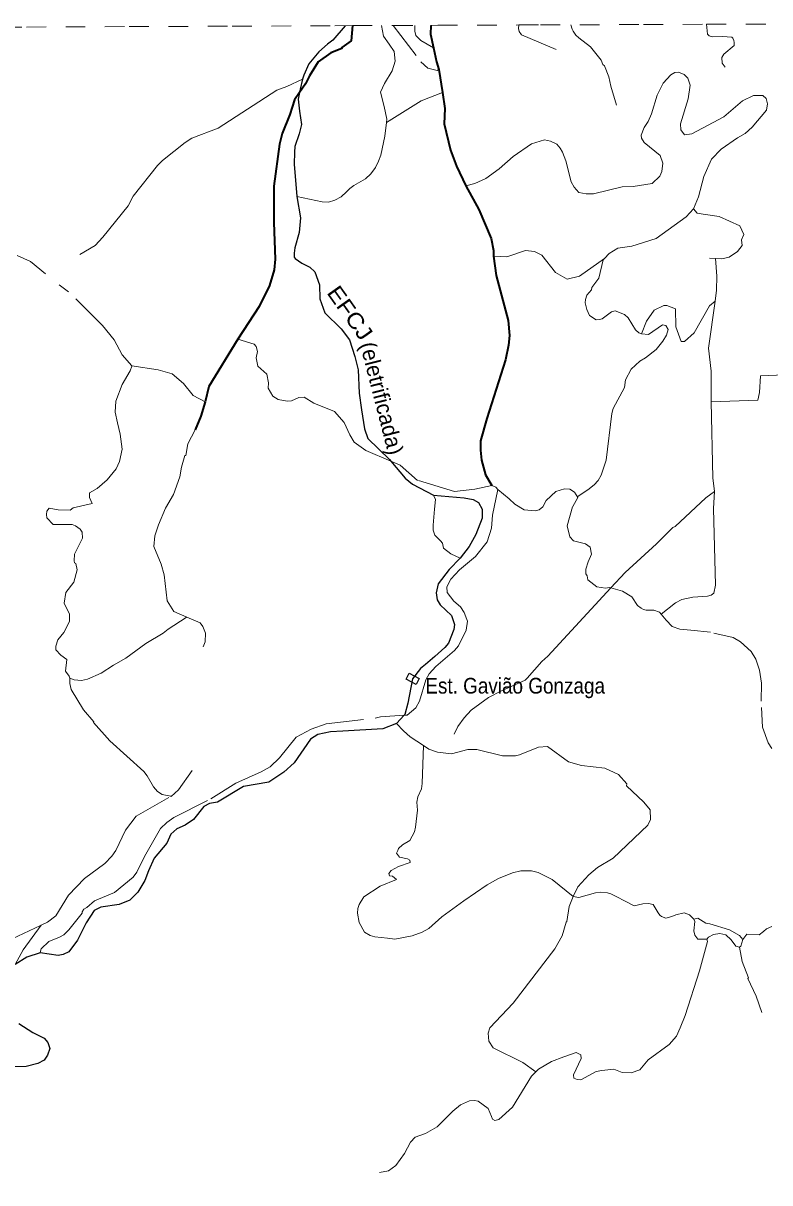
# Model space of a CAD drawing. Extents: x 423 to 448.8, y 7456.3 to 7484.
# Drawn here: x 436.07 to 439.88, y 7478.1 to 7484.01 of the extents above; entities that cross this region are included whole.
import ezdxf
from ezdxf.enums import TextEntityAlignment as Align

# ---------------------------------------------------------------- set-up
doc = ezdxf.new("R2010")
doc.units = 0
doc.header["$LTSCALE"] = 0.032
for name, pattern in [('LONG_DASHED', [7.5, 6, -1.5]), ('MEDIUM_DASHED', [4.5, 3, -1.5]), ('SHORT_DASHED', [2.7, 1.5, -1.2])]:
    doc.linetypes.add(name, pattern=pattern)
for name, color, linetype, lineweight in [('15', 7, 'Continuous', 25), ('2', 7, 'Continuous', 35), ('28', 7, 'Continuous', 25), ('35', 7, 'SHORT_DASHED', 13), ('5', 7, 'LONG_DASHED', 13), ('6', 7, 'MEDIUM_DASHED', 13), ('7', 7, 'Continuous', 13)]:
    doc.layers.add(name, color=color, linetype=linetype, lineweight=lineweight)
doc.layers.add('61', color=7, linetype='Continuous')

msp = doc.modelspace()

# ---------------------------------------------------------------- linework, layer by layer
at = {"layer": '15'}
for points in [[(437.7138, 7483.9944), (437.6506, 7483.9214), (437.6237, 7483.8998), (437.5792, 7483.862), (437.5283, 7483.8001), (437.5023, 7483.7419), (437.4969, 7483.7213), (437.4837, 7483.6711), (437.4807, 7483.6534), (437.475, 7483.6196), (437.4803, 7483.5594), (437.4915, 7483.4905), (437.4798, 7483.444), (437.4567, 7483.3794), (437.4548, 7483.35), (437.4536, 7483.2887), (437.4671, 7483.1237), (437.4865, 7483.0149), (437.4794, 7482.9405), (437.4572, 7482.8629), (437.4545, 7482.8364), (437.4535, 7482.8225), (437.4545, 7482.8148), (437.4585, 7482.8082), (437.4934, 7482.7843), (437.5337, 7482.7649), (437.5586, 7482.741), (437.5825, 7482.6742), (437.585, 7482.6029), (437.6103, 7482.5325), (437.6934, 7482.451), (437.7357, 7482.3946), (437.7627, 7482.3094), (437.7795, 7482.241), (437.7856, 7482.1232), (437.7961, 7482.038), (437.8125, 7481.9408), (437.8289, 7481.8915), (437.939, 7481.7853), (437.947, 7481.7757), (438.0191, 7481.6901), (438.0559, 7481.6582), (438.1629, 7481.6029), (438.3194, 7481.59), (438.3653, 7481.5813), (438.3936, 7481.5648), (438.4113, 7481.5316), (438.4122, 7481.4853), (438.3798, 7481.4029), (438.3449, 7481.3422), (438.2989, 7481.2825), (438.2443, 7481.2246), (438.1877, 7481.1508), (438.1767, 7481.106), (438.1822, 7481.0689), (438.1983, 7481.0447), (438.255, 7480.9897), (438.2714, 7480.9443), (438.2674, 7480.9193), (438.2396, 7480.8488), (438.2207, 7480.8265), (438.1707, 7480.7817), (438.1236, 7480.7407), (438.097, 7480.72), (438.0559, 7480.667), (438.0335, 7480.544), (438.017, 7480.4859), (438.0135, 7480.482), (437.9759, 7480.4401), (437.9058, 7480.4132), (437.7025, 7480.4), (437.6393, 7480.3971), (437.5752, 7480.3841), (437.5372, 7480.3602), (437.4547, 7480.2401), (437.4019, 7480.1912), (437.3248, 7480.1409), (437.1964, 7480.118), (437.0625, 7480.0388), (437.0222, 7480.0324), (436.9933, 7480.0174), (436.9416, 7479.9506), (436.8993, 7479.9212), (436.8555, 7479.9033), (436.8256, 7479.8754), (436.8047, 7479.8305), (436.7413, 7479.7535), (436.7124, 7479.6886), (436.6932, 7479.6391), (436.6579, 7479.5808), (436.6171, 7479.5389), (436.5619, 7479.5185), (436.4695, 7479.5039), (436.4352, 7479.4876), (436.3939, 7479.4249), (436.3501, 7479.3365), (436.3053, 7479.277), (436.2775, 7479.263), (436.2514, 7479.2583), (436.1598, 7479.2719), (436.092, 7479.2491)], [(436.092, 7479.2491), (436.0323, 7479.2122)], [(436.0507, 7478.9116), (436.1219, 7478.8653), (436.18, 7478.8372), (436.1993, 7478.8145), (436.2093, 7478.7841), (436.1974, 7478.7502), (436.1806, 7478.7255), (436.1474, 7478.7078), (436.0894, 7478.6929), (436.0138, 7478.6899)]]:
    msp.add_lwpolyline(points, dxfattribs=at)
at = {"layer": '2'}
for points in [[(437.7508, 7483.9946), (437.7449, 7483.9172), (437.6963, 7483.8835), (437.6968, 7483.8788), (437.641, 7483.8557), (437.5765, 7483.8101), (437.5312, 7483.7394), (437.5108, 7483.6986), (437.4807, 7483.6534), (437.4562, 7483.6166), (437.4321, 7483.5429), (437.3919, 7483.4452), (437.379, 7483.3902), (437.3507, 7483.1772), (437.3498, 7482.9917), (437.3567, 7482.8045), (437.3524, 7482.7512), (437.3275, 7482.6705), (437.2759, 7482.564), (437.1662, 7482.3978), (437.0199, 7482.1557), (437.0013, 7482.0778), (436.9791, 7482.0056), (436.9495, 7481.9352)], [(438.1502, 7483.9962), (438.1491, 7483.9506), (438.1636, 7483.8811), (438.1784, 7483.8101), (438.1915, 7483.7708), (438.2089, 7483.6534), (438.2208, 7483.5731), (438.2176, 7483.4947), (438.2499, 7483.361), (438.28, 7483.2786), (438.3288, 7483.1789), (438.3942, 7483.0587), (438.457, 7482.9098), (438.469, 7482.8493), (438.47, 7482.8201), (438.4827, 7482.722), (438.5436, 7482.4919), (438.5505, 7482.4163), (438.5462, 7482.3665), (438.5308, 7482.2926), (438.4346, 7481.9928), (438.4036, 7481.8804), (438.4028, 7481.8323), (438.4088, 7481.7807), (438.4294, 7481.7069), (438.4602, 7481.6527)]]:
    msp.add_lwpolyline(points, dxfattribs=at)
at = {"layer": '28'}
msp.add_lwpolyline([(438.0402, 7480.6953), (438.0907, 7480.6688), (438.075, 7480.6388), (438.0245, 7480.6653)], close=True, dxfattribs=at)
at = {"layer": '35'}
for points in [[(435.5128, 7483.9852), (435.5662, 7483.9854), (436.09, 7483.9876), (436.6139, 7483.9898), (437.1378, 7483.992), (437.6616, 7483.9942), (437.7508, 7483.9946), (437.9587, 7483.9954), (438.1502, 7483.9962)], [(438.1502, 7483.9962), (438.1855, 7483.9963), (438.5987, 7483.998)], [(438.5987, 7483.998), (438.7093, 7483.9984), (439.2332, 7484.0005), (439.5546, 7484.0018)], [(439.5546, 7484.0018), (439.7571, 7484.0026), (440.2809, 7484.0047), (440.8048, 7484.0067), (440.9332, 7484.0072)]]:
    msp.add_lwpolyline(points, dxfattribs=at)
at = {"layer": '5'}
for points in [[(437.8985, 7483.9951), (437.9098, 7483.9407), (437.9376, 7483.9009), (437.9634, 7483.863), (437.9692, 7483.8136), (437.9536, 7483.7646), (437.9146, 7483.7004), (437.8937, 7483.6555), (437.9125, 7483.5827), (437.9255, 7483.5179), (437.9238, 7483.5016), (437.9165, 7483.4311), (437.8946, 7483.3354), (437.8835, 7483.3039)], [(437.9587, 7483.9954), (438.0988, 7483.811), (438.1351, 7483.7786), (438.1819, 7483.7657), (438.1915, 7483.7708)], [(438.0686, 7483.9958), (438.0683, 7483.9662), (438.0744, 7483.9439), (438.0997, 7483.9191), (438.1636, 7483.8811)], [(438.5987, 7483.998), (438.5969, 7483.9794), (438.6005, 7483.9647), (438.6118, 7483.9475), (438.8434, 7483.8505)], [(439.0967, 7483.5888), (439.0673, 7483.6858), (439.0572, 7483.7346), (439.0349, 7483.7904), (439.0271, 7483.7964), (439.0177, 7483.8188), (438.9627, 7483.8866), (438.9043, 7483.9321), (438.8885, 7483.9466), (438.875, 7483.9665), (438.87, 7483.977), (438.8639, 7483.999)], [(439.5546, 7484.0018), (439.5588, 7483.952), (439.5677, 7483.9434), (439.583, 7483.9375), (439.6355, 7483.9398), (439.6826, 7483.9363), (439.6888, 7483.9303), (439.6931, 7483.9188), (439.6957, 7483.9084), (439.6948, 7483.8935), (439.6431, 7483.85), (439.6321, 7483.8324), (439.6338, 7483.8044), (439.6495, 7483.7835)], [(437.0013, 7482.0778), (436.9387, 7482.1108), (436.8906, 7482.172), (436.8323, 7482.2216), (436.7609, 7482.242), (436.6269, 7482.2621), (436.5774, 7482.3175), (436.5366, 7482.3934), (436.4769, 7482.4672), (436.305, 7482.6387), (436.2569, 7482.6737)], [(436.1598, 7479.2719), (436.1604, 7479.2739), (436.1654, 7479.2914), (436.2033, 7479.3287), (436.2583, 7479.351), (436.2797, 7479.3639), (436.3055, 7479.3879), (436.3742, 7479.4738), (436.3733, 7479.4807), (436.3819, 7479.4936), (436.3982, 7479.5022), (436.436, 7479.5365), (436.5385, 7479.5786), (436.6344, 7479.6568), (436.6524, 7479.6817), (436.6923, 7479.7627), (436.7736, 7479.905), (436.8053, 7479.9359), (436.8416, 7479.9605), (437.0286, 7480.0562), (437.1566, 7480.1352), (437.2854, 7480.1927), (437.331, 7480.2185), (437.379, 7480.264), (437.4648, 7480.3698), (437.5397, 7480.4108), (437.617, 7480.4383), (437.866, 7480.4675), (437.8941, 7480.4744), (438.0135, 7480.482), (438.0292, 7480.483), (438.0738, 7480.5199), (438.0918, 7480.5543), (438.1253, 7480.6625), (438.1408, 7480.6926), (438.176, 7480.7303), (438.2705, 7480.8111), (438.2903, 7480.836), (438.3298, 7480.915), (438.3367, 7480.9605), (438.334, 7480.97), (438.3203, 7481.0052), (438.3013, 7481.0338), (438.268, 7481.063), (438.2338, 7481.1066), (438.2319, 7481.1358), (438.2522, 7481.1748), (438.2959, 7481.2227), (438.3775, 7481.2905), (438.4373, 7481.3657), (438.4586, 7481.4355), (438.4638, 7481.5006), (438.4908, 7481.6314), (438.4815, 7481.6444), (438.4602, 7481.6527), (438.3742, 7481.6333), (438.2705, 7481.6212), (438.0819, 7481.6783), (437.9931, 7481.7561), (437.947, 7481.7757), (437.8191, 7481.8303), (437.7599, 7481.8731), (437.7379, 7481.9106), (437.7081, 7481.9732), (437.66, 7482.0289), (437.5534, 7482.071), (437.5044, 7482.1028), (437.4778, 7482.1011), (437.44, 7482.083), (437.4177, 7482.0822), (437.373, 7482.0899), (437.3447, 7482.1071), (437.3206, 7482.1483), (437.3224, 7482.1744), (437.315, 7482.2186), (437.2687, 7482.2594), (437.2604, 7482.3025), (437.2678, 7482.334), (437.2597, 7482.3596), (437.2493, 7482.3716), (437.1662, 7482.3978)], [(436.9495, 7481.9352), (436.9125, 7481.8647), (436.9014, 7481.8054), (436.8977, 7481.8054), (436.8792, 7481.746), (436.871, 7481.6957), (436.8385, 7481.607), (436.7978, 7481.5365), (436.7624, 7481.4509), (436.7435, 7481.396), (436.7383, 7481.341), (436.7761, 7481.2517), (436.7916, 7481.1967), (436.8067, 7481.0643), (436.8414, 7481.0103), (436.9072, 7480.9821), (436.9754, 7480.9528), (436.9891, 7480.9339), (437.003, 7480.8993), (437.0011, 7480.8564), (436.99, 7480.8298)], [(436.1644, 7479.4118), (436.1968, 7479.4271), (436.2403, 7479.4595), (436.3046, 7479.5658), (436.3862, 7479.6508), (436.4901, 7479.7272), (436.5245, 7479.7641), (436.5451, 7479.7934), (436.5949, 7479.8964), (436.6486, 7479.9684), (436.8268, 7480.0682), (436.8646, 7480.1025), (436.9341, 7480.2004)], [(436.1644, 7479.4118), (436.1624, 7479.4108), (435.9701, 7479.3194), (435.9024, 7479.3003), (435.7206, 7479.321), (435.6021, 7479.345), (435.5591, 7479.3442), (435.5231, 7479.3253), (435.508, 7479.2673), (435.5064, 7479.2611), (435.5092, 7479.2351), (435.5286, 7479.1744), (435.6742, 7479.0513), (435.7103, 7478.9861), (435.7511, 7478.8627), (435.766, 7478.7426), (435.782, 7478.4926), (435.7801, 7478.418), (435.7662, 7478.3415), (435.744, 7478.266), (435.7079, 7478.196), (435.6699, 7478.1428), (435.6394, 7478.077)], [(436.0323, 7479.2122), (436.0728, 7479.2872), (436.1644, 7479.4118)]]:
    msp.add_lwpolyline(points, dxfattribs=at)
at = {"layer": '6'}
for points in [[(436.0422, 7482.8245), (436.1102, 7482.7932), (436.2569, 7482.6737)], [(438.6838, 7481.5228), (438.6255, 7481.529), (438.5776, 7481.5569), (438.5488, 7481.5834), (438.4908, 7481.6314)], [(439.8868, 7480.3129), (439.8688, 7480.3413), (439.8396, 7480.4211), (439.8328, 7480.5534), (439.8344, 7480.6453), (439.825, 7480.7106), (439.8052, 7480.7673), (439.7821, 7480.8059), (439.7271, 7480.8557), (439.6899, 7480.8783), (439.5749, 7480.9047), (439.4744, 7480.9147), (439.4185, 7480.9209), (439.3793, 7480.9341), (439.3484, 7480.9661), (439.3239, 7480.9963), (439.3154, 7481.0068), (439.2861, 7481.0165), (439.2467, 7481.0173), (439.2334, 7481.0199), (439.2207, 7481.0267), (439.2026, 7481.0413), (439.1738, 7481.0852), (439.126, 7481.1141), (439.0665, 7481.1304), (439.0598, 7481.1323), (439.0392, 7481.1289), (438.9962, 7481.1357), (438.9507, 7481.1718), (438.9473, 7481.1915), (438.9404, 7481.2027), (438.9395, 7481.2259), (438.9509, 7481.2633), (438.9685, 7481.3026), (438.9619, 7481.3375), (438.9378, 7481.3556), (438.8768, 7481.371), (438.8585, 7481.391), (438.8448, 7481.4471), (438.8726, 7481.5457), (438.8983, 7481.5918), (438.8824, 7481.6182), (438.8577, 7481.6326), (438.8304, 7481.6354), (438.7875, 7481.6222), (438.7381, 7481.5754), (438.72, 7481.544), (438.7023, 7481.5283), (438.6838, 7481.5228)]]:
    msp.add_lwpolyline(points, dxfattribs=at)
at = {"layer": '7'}
msp.add_line((439.5691, 7482.8103), (439.6007, 7482.8088), dxfattribs=at)
for points in [[(438.3288, 7483.1789), (438.3741, 7483.1912), (438.4296, 7483.2163), (438.4989, 7483.2647), (438.5694, 7483.328), (438.663, 7483.3927), (438.7283, 7483.4133), (438.7592, 7483.4065), (438.7927, 7483.3902), (438.809, 7483.3704), (438.821, 7483.3507), (438.8373, 7483.306), (438.8657, 7483.1986), (438.8803, 7483.172), (438.9043, 7483.1454), (438.9413, 7483.1377), (438.9782, 7483.1377), (439.1242, 7483.1729), (439.18, 7483.1746), (439.2771, 7483.191), (439.3174, 7483.2287), (439.3261, 7483.2519), (439.3312, 7483.2948), (439.3175, 7483.3326), (439.2376, 7483.3996), (439.2238, 7483.4211), (439.2213, 7483.4374), (439.2367, 7483.4752), (439.2564, 7483.5061), (439.2736, 7483.5456), (439.3037, 7483.641), (439.3329, 7483.7019), (439.3724, 7483.744), (439.393, 7483.7561), (439.411, 7483.7578), (439.4411, 7483.7458), (439.4591, 7483.7269), (439.4712, 7483.6916), (439.4609, 7483.6221), (439.4222, 7483.495), (439.4231, 7483.4641), (439.4429, 7483.4391), (439.4797, 7483.4435), (439.6428, 7483.5302), (439.7374, 7483.6109), (439.7941, 7483.6393), (439.8405, 7483.6384), (439.8576, 7483.6238), (439.8654, 7483.5963), (439.8603, 7483.5645), (439.7864, 7483.4769), (439.7512, 7483.4452), (439.7116, 7483.4237), (439.6283, 7483.3661), (439.5803, 7483.3146), (439.5408, 7483.2261), (439.5132, 7483.1231), (439.4875, 7483.0621)], [(437.4969, 7483.7213), (437.4165, 7483.6842), (437.3655, 7483.6668), (437.0675, 7483.4728), (436.9333, 7483.422), (436.8981, 7483.3996), (436.783, 7483.3069), (436.7581, 7483.282), (436.6343, 7483.1254), (436.6084, 7483.0766), (436.479, 7482.9164), (436.4403, 7482.8741), (436.3621, 7482.8283)], [(437.9238, 7483.5016), (438.1005, 7483.612), (438.2089, 7483.6534)], [(437.8835, 7483.3039), (437.8682, 7483.2723), (437.8451, 7483.2395), (437.8175, 7483.2135), (437.7579, 7483.1803), (437.7381, 7483.1643), (437.7207, 7483.1474), (437.6934, 7483.1234), (437.6606, 7483.1051), (437.6285, 7483.0963), (437.5972, 7483.0972), (437.4671, 7483.1237)], [(439.4875, 7483.0621), (439.4506, 7483.0208), (439.2977, 7482.911), (439.1732, 7482.8714), (439.1028, 7482.8611), (439.0581, 7482.8345), (439.0349, 7482.8087)], [(439.6007, 7482.8088), (439.6318, 7482.8073), (439.6691, 7482.8157), (439.7129, 7482.8446), (439.7368, 7482.8745), (439.7333, 7482.9039), (439.7443, 7482.9308), (439.7244, 7482.9747), (439.6194, 7483.0221), (439.5368, 7483.034), (439.5068, 7483.04), (439.4875, 7483.0621)], [(439.0349, 7482.8087), (438.9069, 7482.718), (438.8451, 7482.7036), (438.7859, 7482.7368), (438.715, 7482.8247), (438.6783, 7482.8435), (438.6316, 7482.8489), (438.5375, 7482.8175), (438.47, 7482.8201)], [(439.0349, 7482.8087), (439.0288, 7482.8019), (439.0066, 7482.7091), (438.9705, 7482.6602), (438.9679, 7482.649), (438.9447, 7482.6215), (438.9378, 7482.6001), (438.9361, 7482.582), (438.9447, 7482.5485), (438.9585, 7482.5184), (438.9919, 7482.4961), (439.01, 7482.497), (439.0228, 7482.5013), (439.0701, 7482.5365), (439.0898, 7482.5417), (439.1371, 7482.5228), (439.1551, 7482.5064), (439.1929, 7482.4455), (439.2101, 7482.4291), (439.2225, 7482.4239)], [(439.6007, 7482.8088), (439.6078, 7482.7186), (439.606, 7482.6473), (439.5978, 7482.5906)], [(439.2225, 7482.4239), (439.248, 7482.4897), (439.2873, 7482.5458), (439.3378, 7482.5683), (439.3527, 7482.5692), (439.396, 7482.552), (439.3982, 7482.461), (439.4258, 7482.3859), (439.4429, 7482.3855), (439.4911, 7482.429), (439.5693, 7482.5678), (439.5978, 7482.5906)], [(439.5978, 7482.5906), (439.5648, 7482.3518), (439.5785, 7482.2342), (439.5775, 7482.0776)], [(439.2225, 7482.4239), (439.2594, 7482.4219), (439.331, 7482.4698), (439.347, 7482.4668), (439.3589, 7482.4468), (439.3499, 7482.4179), (439.332, 7482.388), (439.2972, 7482.3441), (439.2436, 7482.302), (439.2152, 7482.2857), (439.1714, 7482.2445), (439.1422, 7482.1904), (439.1371, 7482.1509), (439.0787, 7482.0444), (439.0718, 7482.0195), (439.0435, 7481.7807), (439.0177, 7481.7052), (439.0022, 7481.6768), (438.9816, 7481.6553), (438.9507, 7481.6296), (438.9, 7481.5978), (438.8983, 7481.5918)], [(436.6269, 7482.2621), (436.6263, 7482.2601), (436.619, 7482.2368), (436.5776, 7482.1665), (436.5449, 7482.0812), (436.5417, 7482.0255), (436.5536, 7481.9706), (436.5675, 7481.9138), (436.578, 7481.8376), (436.5649, 7481.7739), (436.5468, 7481.7369), (436.5013, 7481.6811), (436.4497, 7481.6373), (436.4111, 7481.6149), (436.4111, 7481.5909), (436.4257, 7481.56), (436.3287, 7481.5388), (436.3123, 7481.5273), (436.2522, 7481.5282), (436.2058, 7481.5368), (436.1938, 7481.5218), (436.1919, 7481.5044), (436.1944, 7481.4877), (436.2262, 7481.4538), (436.3227, 7481.4534), (436.3399, 7481.4461), (436.3639, 7481.4296), (436.374, 7481.4147), (436.376, 7481.3838), (436.3356, 7481.3023), (436.333, 7481.268), (436.3355, 7481.2577), (436.3415, 7481.2551), (436.348, 7481.222), (436.332, 7481.1601), (436.2907, 7481.1078), (436.2822, 7481.0522), (436.3101, 7480.9966), (436.3101, 7480.9594), (436.2805, 7480.9039), (436.2505, 7480.866), (436.2393, 7480.8343), (436.2393, 7480.8154), (436.2645, 7480.7886), (436.2952, 7480.7664), (436.2892, 7480.7063), (436.3071, 7480.6803), (436.3112, 7480.6709)], [(439.5775, 7482.0776), (439.8164, 7482.0866), (439.8241, 7482.1254), (439.8292, 7482.2103), (440.1159, 7482.2225), (440.1846, 7482.2205), (440.3055, 7482.231), (440.3483, 7482.229), (440.6569, 7482.24), (440.6882, 7482.2367)], [(439.5775, 7482.0776), (439.5871, 7481.6914), (439.5948, 7481.6218)], [(438.1629, 7481.6029), (438.1735, 7481.5809), (438.1694, 7481.5318), (438.1626, 7481.4499), (438.1612, 7481.4254), (438.1709, 7481.3999), (438.2, 7481.3704), (438.2099, 7481.3581), (438.2152, 7481.3337), (438.2514, 7481.3034), (438.2989, 7481.2825)], [(439.5948, 7481.6218), (439.5506, 7481.5894), (439.3939, 7481.4432), (439.3836, 7481.4389), (439.2994, 7481.3547), (439.1396, 7481.2096), (439.0665, 7481.1304), (438.7455, 7480.7827), (438.7154, 7480.7553), (438.6415, 7480.6702), (438.6304, 7480.6608), (438.5096, 7480.6064), (438.4439, 7480.5715), (438.3558, 7480.5082), (438.3195, 7480.4693), (438.2877, 7480.4246), (438.2688, 7480.3851)], [(439.5948, 7481.6218), (439.5905, 7481.5351), (439.6009, 7481.1443), (439.5914, 7481.1031), (439.5777, 7481.0928), (439.5597, 7481.0876), (439.4841, 7481.0833), (439.4291, 7481.0713), (439.3956, 7481.0541), (439.3239, 7480.9963)], [(436.3112, 7480.6709), (436.3331, 7480.6621), (436.3709, 7480.6594), (436.4006, 7480.6649), (436.4704, 7480.6969), (436.5339, 7480.7372), (436.5958, 7480.7733), (436.698, 7480.8471), (436.7864, 7480.9004), (436.8113, 7480.921), (436.9038, 7480.9797), (436.9072, 7480.9821)], [(436.3112, 7480.6709), (436.3111, 7480.6434), (436.3171, 7480.6135), (436.3807, 7480.5085), (436.4334, 7480.448), (436.4317, 7480.4444), (436.515, 7480.3507), (436.6877, 7480.1944), (436.7057, 7480.1738), (436.7366, 7480.1171), (436.7572, 7480.0931), (436.7822, 7480.0785), (436.8248, 7480.0687), (436.8268, 7480.0682)], [(437.9759, 7480.4401), (438.0105, 7480.4015), (438.0452, 7480.3722), (438.1127, 7480.3271)], [(438.1127, 7480.3271), (438.1065, 7480.1343), (438.1022, 7480.1077), (438.0833, 7480.0665), (438.0786, 7480.0386), (438.0821, 7479.999), (438.0724, 7479.9121), (438.0671, 7479.887), (438.0424, 7479.8438), (438.0059, 7479.8214), (437.9856, 7479.8028), (437.982, 7479.7935), (437.9751, 7479.7791), (437.9906, 7479.7583), (438.0312, 7479.7499), (438.0437, 7479.7437), (438.0447, 7479.7308), (437.9846, 7479.7112), (437.9487, 7479.6912), (437.9358, 7479.6753), (437.9388, 7479.6633), (437.9547, 7479.6623), (437.9751, 7479.6447), (437.8926, 7479.6104), (437.8085, 7479.5563), (437.7844, 7479.5176), (437.7784, 7479.4979), (437.7767, 7479.4739), (437.7853, 7479.4258), (437.8119, 7479.3768), (437.8403, 7479.3605), (437.8656, 7479.3524), (437.9287, 7479.3466), (437.9667, 7479.3419), (438.0558, 7479.3579), (438.1056, 7479.3768), (438.14, 7479.3957), (438.2069, 7479.4541), (438.3186, 7479.5366), (438.4363, 7479.6181), (438.4955, 7479.6499), (438.5659, 7479.6783), (438.6089, 7479.6886), (438.663, 7479.6886), (438.6974, 7479.6802), (438.7686, 7479.6456), (438.8758, 7479.5589)], [(438.1127, 7480.3271), (438.1395, 7480.3093), (438.1838, 7480.2943), (438.2551, 7480.2849), (438.3394, 7480.3073), (438.3848, 7480.3078), (438.5144, 7480.2751), (438.5806, 7480.2752), (438.602, 7480.2795), (438.6991, 7480.319), (438.7438, 7480.3224), (438.852, 7480.2451), (438.9172, 7480.2253), (439.0366, 7480.2125), (439.1053, 7480.1807), (439.1482, 7480.1326), (439.1465, 7480.1214), (439.2356, 7480.0384), (439.2668, 7479.9995), (439.2693, 7479.9504), (439.2563, 7479.9225), (439.0791, 7479.753), (438.9997, 7479.7066), (438.955, 7479.6688), (438.8992, 7479.607), (438.8758, 7479.5589)], [(438.8758, 7479.5589), (438.8549, 7479.508), (438.8435, 7479.4308), (438.8391, 7479.4283), (438.8193, 7479.3588), (438.7815, 7479.2926), (438.5702, 7479.0153), (438.4509, 7478.889), (438.4414, 7478.8624), (438.4457, 7478.822), (438.4672, 7478.7876), (438.6192, 7478.7129), (438.6858, 7478.6656)], [(438.8758, 7479.5589), (438.9041, 7479.5538), (438.9887, 7479.5767), (439.0152, 7479.5797), (439.0495, 7479.5773), (439.0673, 7479.5716), (439.0907, 7479.5609), (439.1431, 7479.5326), (439.1857, 7479.5108), (439.2307, 7479.5203), (439.2592, 7479.5228), (439.2826, 7479.5171), (439.3084, 7479.4757), (439.3162, 7479.4627), (439.3251, 7479.457), (439.3471, 7479.4473), (439.3783, 7479.4563), (439.3985, 7479.4652), (439.4403, 7479.4747), (439.4685, 7479.4654), (439.4892, 7479.4422)], [(439.4892, 7479.4422), (439.5094, 7479.4483), (439.5512, 7479.4221), (439.5705, 7479.4191), (439.6714, 7479.3886), (439.7219, 7479.3594), (439.7391, 7479.3394)], [(439.4892, 7479.4422), (439.4948, 7479.4304), (439.4892, 7479.3827), (439.4942, 7479.3607), (439.5099, 7479.3414), (439.5564, 7479.3414)], [(439.7219, 7479.2996), (439.7033, 7479.3062), (439.6794, 7479.3381), (439.6528, 7479.3633), (439.6223, 7479.37), (439.5904, 7479.3651), (439.5652, 7479.3514), (439.5564, 7479.3414)], [(439.7391, 7479.3394), (439.7597, 7479.3663), (439.8228, 7479.3625), (439.8453, 7479.3809), (439.8596, 7479.3938), (439.8878, 7479.4062)], [(438.6858, 7478.6656), (438.6987, 7478.6789), (438.7645, 7478.7176), (438.8268, 7478.7423), (438.8899, 7478.763), (438.9143, 7478.7514), (438.9151, 7478.7325), (438.8771, 7478.6495), (438.8791, 7478.6336), (438.8959, 7478.6257), (438.9146, 7478.6237), (438.9927, 7478.6673), (439.0213, 7478.6722), (439.0815, 7478.6791), (439.1245, 7478.6623), (439.1709, 7478.6603), (439.2143, 7478.6751), (439.2573, 7478.7265), (439.364, 7478.8037), (439.401, 7478.8462), (439.4205, 7478.8899), (439.4463, 7478.9517), (439.5184, 7479.1802), (439.5588, 7479.3296), (439.5564, 7479.3414)], [(439.7391, 7479.3394), (439.7285, 7479.3062), (439.7219, 7479.2996)], [(439.7219, 7479.2996), (439.7365, 7479.2279), (439.7677, 7479.1444), (439.7657, 7479.1406), (439.8078, 7479.0513), (439.8362, 7478.968)], [(438.6858, 7478.6656), (438.6633, 7478.6426), (438.566, 7478.4846), (438.4964, 7478.4218), (438.4766, 7478.4166), (438.4636, 7478.4248), (438.4588, 7478.4375), (438.4413, 7478.4782), (438.391, 7478.5161), (438.3729, 7478.52), (438.3477, 7478.5169), (438.3015, 7478.4967), (438.2616, 7478.4648), (438.1825, 7478.3846), (438.1228, 7478.3507), (438.0705, 7478.3323), (438.0457, 7478.3064), (438.0158, 7478.2485), (437.9725, 7478.1882), (437.9337, 7478.1613), (437.8884, 7478.1529)]]:
    msp.add_lwpolyline(points, dxfattribs=at)

# ---------------------------------------------------------------- texts
at = {"layer": '61', "width": 1.15}
msp.add_text('EFCJ', height=0.08, rotation=305.319, dxfattribs=at).set_placement((437.7058, 7482.5085), align=Align.CENTER)
at = {"layer": '61'}
msp.add_text('(eletrificada)', height=0.08, rotation=284.386, dxfattribs=at).set_placement((437.8617, 7482.0867), align=Align.CENTER)
at = {"layer": '61', "width": 0.9}
msp.add_text('Est. Gavião Gonzaga', height=0.08, dxfattribs=at).set_placement((438.1221, 7480.5922))

doc.saveas('drawing.dxf')
